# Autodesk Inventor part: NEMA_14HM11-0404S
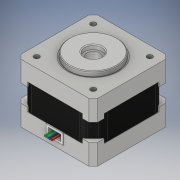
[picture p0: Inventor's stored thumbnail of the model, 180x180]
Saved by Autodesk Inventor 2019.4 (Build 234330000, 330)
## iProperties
Created: 2019-11
Part Number: NEMA_14HM11-0404S
Material: Générique
Document SubType Name: Modeling
Designer: thoma
Density: 1 g/cm^3
Appearance: Usiné - Aluminium
Author: thoma
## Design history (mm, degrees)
sketch "Esquisse1"
  geometry: L1 (-15.6, 17.6)-(15.6, 17.6); L2 (17.6, 15.6)-(17.6, -15.6); L3 (15.6, -17.6)-(-15.6, -17.6); L4 (-17.6, -15.6)-(-17.6, 15.6); L5 (-17.6, 17.6)-(17.6, -17.6); L6 (17.6, 17.6)-(-17.6, -17.6); L7 (17.6, 15.6)-(15.6, 17.6); L8 (-17.6, 15.6)-(-15.6, 17.6); L9 (-17.6, -15.6)-(-15.6, -17.6); L10 (17.6, -15.6)-(15.6, -17.6); 1 further point
  constraints: 20 end point, 8 point on line, 2 midpoint, 2 parallel, 1 horizontal, 1 perpendicular
  dimensions: "d0" = 35.2 distance of L5.end L6.end; "d1" = 35.2 distance of L6.start L5.end; "d2" = 2 distance of L2.start L6.start; "d3" = 2 distance of L1.end L6.start (= d2); "d4" = 2 distance of L4.end L5.start (= d2); "d5" = 2 distance of L1.start L5.start (= d4); "d6" = 2 distance of L4.start L6.end (= d2); "d7" = 2 distance of L3.end L6.end (= d6); "d8" = 2 distance of L2.end L5.end (= d2); "d9" = 2 distance of L3.start L5.end (= d8)
extrude "Extrusion1" new body sketch "Esquisse1" stored distance "d10" = 27; taper "d11" = 0 deg
sketch "Esquisse2"
  geometry: L1 (-13, -13)-(13, -13); L2 (13, -13)-(13, 13); L3 (13, 13)-(-13, 13); L4 (-13, 13)-(-13, -13); L5 (-13, -13)-(13, 13); L6 (13, -13)-(-13, 13); 5 further points
  constraints: 12 end point, 4 coincident, 2 midpoint, 2 parallel, 1 horizontal, 1 perpendicular
  dimensions: "d12" = 26 distance of L3.end L2.end; "d13" = 26 distance of L2.end L1.end
hole "Perçage1" sketch "Esquisse2" at (-13, 13), (13, 13), (13, -13), (-13, -13) diameter "d14" = 2.459; stored, may be unused: countersink angle "d18" = 90 deg, drill point angle "d20" = 0 deg; dims "d15" = 4.5, "d16" = 3, "d17" = 2, "d19" = 4.5
sketch "Esquisse3"
  geometry: C1 r 11 at (0, 0); 1 further point
  constraints: 1 centre point, 1 coincident
  dimensions: "d21" = 22 diameter of C1
extrude "Extrusion2" join sketch "Esquisse3" distance "d22" = 2; taper "d23" = 0 deg
chamfer "Chanfrein1" distance "d24" = 0.3; stored, may be unused: second distance "d25" = 2, angle "d26" = 45 deg
sketch "Esquisse4"
  geometry: C1 r 11 at (0, 0) reference; C2 r 11 at (0, 0); C3 r 11.75 at (0, 0); 1 further point
  constraints: 2 centre point, 2 coincident
  dimensions: "d27" = 23.5 diameter of C3
extrude "Extrusion3" cut sketch "Esquisse4" distance "d28" = 0.2; taper "d29" = 0 deg
chamfer "Chanfrein2" distance "d30" = 0.2; stored, may be unused: second distance "d31" = 2, angle "d32" = 70 deg
sketch "Esquisse5"
  geometry: C1 r 4 at (0, 0); 1 further point
  constraints: 1 centre point, 1 coincident
  dimensions: "d33" = 8 diameter of C1
extrude "Extrusion4" cut sketch "Esquisse5" distance "d34" = 2; taper "d35" = 0 deg
sketch "Esquisse6"
  geometry: C1 r 3 at (0, 0); 1 further point
  constraints: 1 centre point, 1 coincident
  dimensions: "d36" = 6 diameter of C1
extrude "Extrusion5" cut sketch "Esquisse6" stored distance "d37" = 10; taper "d38" = 0 deg
fillet "Congé1" dims "d39" = 0.4
node "Plan de construction1"
sketch "Esquisse7"
  geometry: L1 (-12.6, -17.6)-(12.6, -17.6); L2 (17.6, -12.6)-(17.6, 12.6); L3 (12.6, 17.6)-(-12.6, 17.6); L4 (-17.6, 12.6)-(-17.6, -12.6); L5 (-17.6, -17.6)-(17.6, 17.6); L6 (17.6, -17.6)-(-17.6, 17.6); L7 (17.6, -12.6)-(12.6, -17.6); L8 (17.6, 12.6)-(12.6, 17.6); L9 (-17.6, 12.6)-(-12.6, 17.6); L10 (-17.6, -12.6)-(-12.6, -17.6); L11 (-15.6, -17.6)-(-17.6, -15.6) reference; L12 (-17.6, -15.6)-(-17.6, 15.6) reference; L13 (-17.6, 15.6)-(-15.6, 17.6) reference; L14 (-15.6, 17.6)-(15.6, 17.6) reference; L15 (15.6, 17.6)-(17.6, 15.6) reference; L16 (17.6, 15.6)-(17.6, -15.6) reference; L17 (17.6, -15.6)-(15.6, -17.6) reference; L18 (15.6, -17.6)-(-15.6, -17.6) reference; 1 further point
  constraints: 20 end point, 8 point on line, 2 midpoint, 2 parallel, 1 horizontal, 1 perpendicular
  dimensions: "d40" = 5 distance of L2.start L6.start; "d41" = 5 distance of L1.end L6.start (= d40); "d42" = 5 distance of L2.end L5.end; "d43" = 5 distance of L3.start L5.end (= d42); "d44" = 5 distance of L4.start L6.end (= d42); "d45" = 5 distance of L3.end L6.end (= d44); "d46" = 5 distance of L4.end L5.start (= d42); "d47" = 5 distance of L1.start L5.start (= d46)
extrude "Extrusion6" cut sketch "Esquisse7" stored distance "d48" = 8; taper "d49" = 0 deg
sketch "Esquisse9"
  geometry: L1 (3, 7.5)-(28.2, 7.5); L2 (28.2, 7.5)-(28.2, 19.5); L3 (28.2, 19.5)-(3, 19.5); L4 (3, 19.5)-(3, 7.5); L5 (3, 7.5)-(28.2, 19.5); L6 (28.2, 7.5)-(3, 19.5); 1 further point
  constraints: 12 end point, 2 midpoint, 2 parallel, 1 horizontal, 1 perpendicular
  dimensions: "d53" = 12 distance of L2.end L1.end
extrude "Extrusion8" cut sketch "Esquisse9" distance "d54" = 0.1; taper "d55" = 0 deg
pattern_circular "Réseau circulaire1" dims angle "d57" = 360 deg
fillet "Congé2" dims "d59" = 4
sketch "Esquisse10"
  geometry: C1 r 3.5 at (0, 0); 1 further point
  constraints: 1 centre point, 1 coincident
  dimensions: "d60" = 7 diameter of C1
extrude "Extrusion9" cut sketch "Esquisse10" distance "d61" = 2; taper "d62" = 0 deg
sketch "Esquisse12"
  geometry: L1 (13, 13)-(-13, 13); L2 (-13, 13)-(-13, -13); L3 (-13, -13)-(13, -13); L4 (13, -13)-(13, 13); L5 (13, 13)-(-13, -13); L6 (-13, 13)-(13, -13); C1 r 1.23 at (-13, -13) reference; 5 further points
  constraints: 12 end point, 4 coincident, 2 midpoint, 2 parallel, 1 horizontal, 1 perpendicular
hole "Perçage3" sketch "Esquisse12" at (13, -13), (-13, -13), (-13, 13), (13, 13) diameter "d70" = 2.459; stored, may be unused: countersink angle "d74" = 90 deg, drill point angle "d76" = 0 deg; dims "d71" = 21, "d72" = 6, "d73" = 2.2, "d75" = 22
fillet "Congé3" dims "d77" = 0.2
sketch "Esquisse13"
  geometry: L1 (11.6, 2.5)-(19.6, 2.5); L2 (19.6, 2.5)-(19.6, 7.5); L3 (4.557, 7.5)-(26.643, 7.5) reference; L4 (11.6, 7.5)-(19.6, 7.5); L5 (11.6, 7.5)-(11.6, 2.5); 2 further points
  constraints: 8 end point, 2 point on line, 1 horizontal, 1 midpoint, 1 parallel, 1 perpendicular
extrude "Extrusion10" cut sketch "Esquisse13" distance "d80" = 2; taper "d81" = 0 deg
sketch "Esquisse14"
  geometry: L1 (19.6, 2.5)-(11.6, 2.5) reference; L2 (19.6, 7.5)-(19.6, 2.5) reference; L3 (11.6, 7.5)-(19.6, 7.5) reference; L4 (11.6, 2.5)-(11.6, 7.5) reference; L5 (19.5, 7.4)-(19.5, 2.6); L6 (19.5, 2.6)-(11.7, 2.6); L7 (11.7, 2.6)-(11.7, 7.4); L8 (11.7, 7.4)-(19.5, 7.4); L9 (18.5, 6.4)-(18.5, 3.6); L10 (18.5, 3.6)-(12.7, 3.6); L11 (12.7, 3.6)-(12.7, 6.4); L12 (12.7, 6.4)-(18.5, 6.4); 1 further point
  constraints: 16 end point, 6 other
  dimensions: "d82" = 0.1 distance between parallel lines of L3 L8; "d83" = 1 distance between parallel lines of L8 L12
extrude "Extrusion11" join sketch "Esquisse14" distance "d84" = 2.2; taper "d85" = 0 deg
sketch "Esquisse15"
  geometry: L1 (12.7, 6.4)-(12.7, 3.6) reference; L2 (12.7, 5)-(18.5, 5); L3 (18.5, 3.6)-(18.5, 6.4) reference; C1 r 0.5 at (15.1, 5); C2 r 0.5 at (16.1, 5); C3 r 0.5 at (17.1, 5); C4 r 0.5 at (14.1, 5); C5 r 0.5 at (15.1, 5); C6 r 0.5 at (16.1, 5); 1 further point
  constraints: 6 centre point, 2 end point, 2 horizontal, 2 midpoint, 10 other
  dimensions: "d94" = 1 distance of C1.centre C2.centre; "d97" = 1 distance of C1.centre C4.centre
extrude "Extrusion12" join sketch "Esquisse15" distance "d100" = 5; taper "d101" = 0 deg
node "Solide1"
node "Boucle projetée1"
node "Boucle projetée2"
